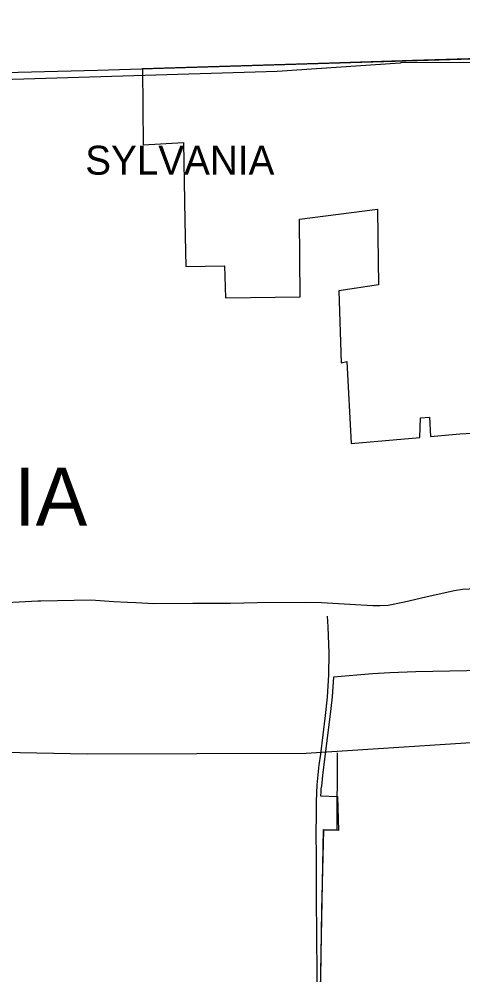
# Model space of a CAD drawing. Extents: x -232 to 448, y 619 to 1059.
# Drawn here: x 113.08 to 128.82, y 925.75 to 959.66 of the extents above; entities that cross this region are included whole.
import ezdxf

# ---------------------------------------------------------------- set-up
doc = ezdxf.new("R2010")
doc.units = 0
doc.layers.add('Default', color=7, linetype='Continuous')

msp = doc.modelspace()

# ---------------------------------------------------------------- linework, layer by layer
at = {"layer": 'Default'}
for points in [[(191.559, 959.664), (178.631, 959.398), (164.124, 958.912), (149.104, 958.636), (143.624, 958.482), (132.12, 958.132), (126.614, 958.11), (126.592, 958.099), (122.234, 957.803), (110.103, 957.439)], [(106.941, 957.63), (115.861, 957.858), (129.538, 958.269), (129.538, 958.269), (133.907, 958.565), (133.928, 958.575), (139.422, 958.598), (145.054, 958.769)], [(133.947, 958.576), (132.929, 958.499), (131.465, 958.399), (129.408, 958.265), (127.029, 958.193)], [(127.029, 958.193), (124.086, 958.105), (117.456, 957.904)], [(117.456, 957.904), (117.472, 955.198), (118.904, 955.292)], [(118.904, 955.292), (118.957, 952.504)], [(123.029, 952.57), (125.793, 952.919)], [(125.793, 952.919), (125.804, 951.968), (125.83, 950.238), (124.414, 950.02)], [(118.957, 952.504), (118.988, 950.881), (120.362, 950.91), (120.395, 949.774), (123.046, 949.807)], [(123.046, 949.807), (123.029, 952.57)], [(124.414, 950.02), (124.504, 947.469), (124.704, 947.516)], [(124.704, 947.516), (124.859, 944.611)], [(127.297, 944.819), (127.317, 945.517), (127.639, 945.536), (127.675, 944.853), (128.708, 944.948)], [(124.859, 944.611), (127.297, 944.819)], [(128.708, 944.948), (130.065, 945.021)], [(117.861, 938.93), (119.236, 938.938), (119.978, 938.942), (120.576, 938.943), (121.517, 938.965), (123.244, 938.981), (123.805, 938.96), (124.811, 938.901), (125.624, 938.858), (125.876, 938.862), (126.169, 938.873), (126.746, 938.987), (127.511, 939.17), (128.505, 939.389), (128.801, 939.441), (130.232, 939.508), (130.961, 939.526)], [(96.269, 939.063), (98.756, 939.086), (100.61, 939.082), (101.512, 939.078), (102.932, 939.054), (104.596, 939.009), (105.449, 939.008), (105.719, 938.998), (107.059, 938.985), (110.73, 938.963), (112.415, 938.958), (113.741, 939.018), (113.85, 939.02)], [(113.85, 939.02), (115.618, 939.056), (116.44, 939.006), (116.92, 938.98), (117.212, 938.964)], [(117.212, 938.964), (117.861, 938.93)], [(123.714, 923.489), (123.675, 924.275), (123.65, 924.788), (123.649, 925.61), (123.641, 927.333), (123.627, 928.289), (123.622, 929.819), (123.618, 930.906), (123.63, 931.3), (123.629, 931.909), (123.655, 932.491), (123.72, 933.201), (123.778, 933.589), (123.941, 934.95), (124.022, 935.605), (124.069, 936.394), (124.077, 937.169), (124.04, 938.101), (124.013, 938.481)], [(132.7, 936.57), (128.966, 936.544), (127.156, 936.506), (126.227, 936.473), (125.618, 936.43), (124.23, 936.312)], [(124.23, 936.312), (124.212, 935.972), (124.188, 935.621), (124.139, 935.202)], [(124.139, 935.202), (123.928, 933.485), (123.844, 932.84), (123.824, 932.683), (123.809, 932.458)], [(131.674, 934.149), (123.263, 933.603), (115.502, 933.584), (112.51, 933.646), (112.513, 933.427)], [(123.745, 923.459), (123.764, 925.219), (123.875, 930.909), (124.356, 930.897), (124.373, 933.632)], [(123.809, 932.458), (123.785, 932.358), (123.785, 932.249), (123.763, 932.107)], [(123.763, 932.107), (124.368, 932.081)], [(124.368, 932.081), (124.408, 930.87)], [(123.88, 930.885), (123.806, 928.062)], [(124.408, 930.87), (123.88, 930.885)], [(123.806, 928.062), (123.767, 925.651), (123.782, 925.123), (123.772, 924.588), (123.778, 924.041), (123.766, 923.865)]]:
    msp.add_lwpolyline(points, dxfattribs=at)

# ---------------------------------------------------------------- texts
for height, p in [(1.026, (115.422, 954.145)), (2.052, (102.071, 941.691))]:
    msp.add_text('SYLVANIA', height=height, dxfattribs=at).set_placement(p)

doc.saveas('drawing.dxf')
